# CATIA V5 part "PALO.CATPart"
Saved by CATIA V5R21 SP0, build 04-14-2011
Part number: PALO
Bounding box of the stored display mesh (mm): x -13.996 to 13.996, y -13.996 to 13.996, z -205 to 205
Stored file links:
  D:\MENA 3D\BISMARK\PALO.CATPart
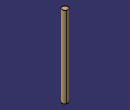
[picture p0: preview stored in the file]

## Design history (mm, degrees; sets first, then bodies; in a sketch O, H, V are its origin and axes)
Body1 (main body)
  Set1
    Sketch1 on yz-plane, origin (0, 0, 0), H (0, 1, 0), V (0, 0, 1)
      point P1 (7, 0)
      line L1 (14, 205) -> (14, -205)
      line L2 (14, -205) -> (0, -205)
      line L3 (0, -205) -> (0, 205)
      line L4 (0, 205) -> (14, 205)
      distance L3 L1 = 14
      distance L4 L2 = 410
      coincidence: P1 H, L3 V
      vertical: L1 V, L3 V
      horizontal: L2 H, L4 H
      equidistance: L1 L3 P1, L2 L4 P1
  Shaft1: profile Sketch1, axis Sketch1.L3, angle 360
